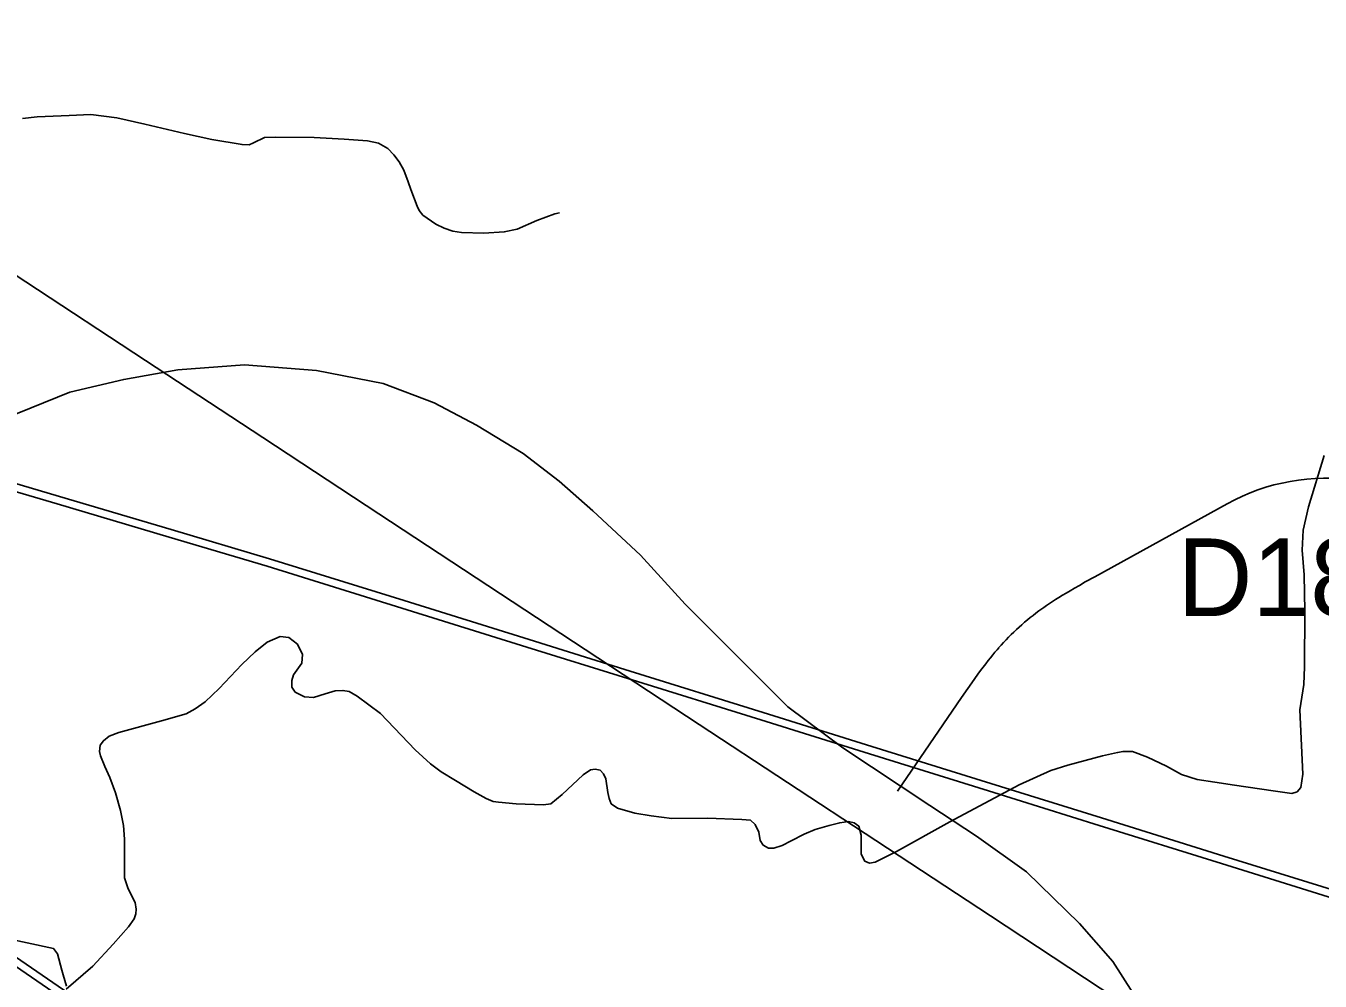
# Model space of a CAD drawing. Extents: x -789162 to -606354, y -1062736 to -945481.
# Drawn here: x -680304 to -677802, y -997921 to -996075 of the extents above; entities that cross this region are included whole.
import ezdxf

# ---------------------------------------------------------------- set-up
doc = ezdxf.new("R2010")
doc.units = 0
for name, color, linetype in [('_SIRSI VZTAHY_ELEKTRICKE VEDENI VN 110 kV S', 7, 'Continuous'), ('_SIRSI VZTAHY_ELEKTRICKE VEDENI VN 400 kV S', 7, 'Continuous'), ('_SIRSI VZTAHY_SILNICE I a II TRIDY_NAVRH POPIS', 7, 'Continuous'), ('_SIRSI VZTAHY_SILNICE I TRIDY_NAVRH', 7, 'Continuous'), ('_SIRSI VZTAHY_SILNICE II TRIDY_REZERVA', 7, 'Continuous'), ('_SIRSI VZTAHY_SILNICE III TRIDY_STAV', 7, 'Continuous'), ('_SIRSI VZTAHY_VTL PLYNOVOD', 7, 'Continuous')]:
    doc.layers.add(name, color=color, linetype=linetype)

msp = doc.modelspace()

# ---------------------------------------------------------------- linework, layer by layer
at = {"layer": '_SIRSI VZTAHY_ELEKTRICKE VEDENI VN 110 kV S'}
for points in [[(-685024.6, -995974.9), (-684755, -996025.3), (-684493.2, -996075.2), (-684240.6, -996121.7), (-684071.4, -996153.5), (-683850.9, -996194), (-683615.6, -996238.7), (-683368.5, -996285.4), (-683140.9, -996327.9), (-682881.3, -996376.3), (-682647.1, -996420.3), (-682428.9, -996460.3), (-682242.2, -996588.2), (-682038.7, -996726.6), (-681844.8, -996858.4), (-681627, -997006.6), (-681415.8, -997150.4), (-681189.1, -997304.7), (-680962, -997459.2), (-680712.5, -997628.8), (-680520.3, -997759.5), (-680366.6, -997864.1), (-680126.8, -998028.5)], [(-685021.9, -995960.1), (-684752.2, -996010.5), (-684490.4, -996060.4), (-684237.8, -996106.9), (-684068.6, -996138.7), (-683848.2, -996179.3), (-683612.8, -996224), (-683365.8, -996270.6), (-683138.2, -996313.1), (-682878.5, -996361.5), (-682644.3, -996405.5), (-682423, -996446.2), (-682233.8, -996575.8), (-682030.3, -996714.2), (-681836.4, -996846), (-681618.5, -996994.2), (-681407.4, -997138), (-681180.7, -997292.3), (-680953.5, -997446.8), (-680704.1, -997616.4), (-680511.8, -997747.1), (-680358.1, -997851.7), (-680114.2, -998019)], [(-677775.7, -997761.4), (-677992.7, -997693.8), (-678228.7, -997620.2), (-678442.9, -997553.6), (-678672.8, -997482), (-678883.3, -997416.4), (-679140.5, -997336.3), (-679335.5, -997275.5), (-679577.6, -997200.1), (-679838.1, -997118.9), (-680027.5, -997062.8), (-680243.8, -996998.8), (-680490, -996926.1)], [(-677775.7, -997761.4), (-677992.7, -997693.8), (-678228.7, -997620.2), (-678442.9, -997553.6), (-678672.8, -997482), (-678883.3, -997416.4), (-679140.5, -997336.3), (-679335.5, -997275.5), (-679577.6, -997200.1), (-679838.1, -997118.9), (-680027.5, -997062.8), (-680243.8, -996998.8), (-680490, -996926.1)], [(-680485.8, -996911.7), (-680239.7, -996984.5), (-680023.2, -997048.4), (-679833.3, -997104.7), (-679573.1, -997185.8), (-679331, -997261.2), (-679136.1, -997322), (-678878.8, -997402.1), (-678668.4, -997467.7), (-678438.5, -997539.2), (-678224.3, -997605.9), (-677988.2, -997679.5), (-677771.4, -997747)], [(-680485.8, -996911.7), (-680239.7, -996984.5), (-680023.2, -997048.4), (-679833.3, -997104.7), (-679573.1, -997185.8), (-679331, -997261.2), (-679136.1, -997322), (-678878.8, -997402.1), (-678668.4, -997467.7), (-678438.5, -997539.2), (-678224.3, -997605.9), (-677988.2, -997679.5), (-677771.4, -997747)]]:
    msp.add_lwpolyline(points, dxfattribs=at)
at = {"layer": '_SIRSI VZTAHY_ELEKTRICKE VEDENI VN 400 kV S'}
msp.add_lwpolyline([(-678166.3, -997975), (-678439.4, -997795), (-678660.8, -997649.5), (-679002.5, -997425.1), (-679222.9, -997280.5), (-679622.1, -997017.8), (-679846.3, -996870.2), (-680073, -996721.2), (-680304.5, -996569.1), (-680758.3, -996270.5), (-680929.3, -996158), (-681000.1, -995927.1), (-681168, -995377.1), (-681221.7, -995201.1), (-681158.1, -994516.5), (-681411, -994089), (-681573.6, -993813.5), (-681729, -993549.7), (-682076.2, -992960.6), (-682198.7, -992719.4), (-682367.5, -992387.1)], dxfattribs=at)
at = {"layer": '_SIRSI VZTAHY_SILNICE I TRIDY_NAVRH'}
msp.add_lwpolyline([(-680430.5, -996867.5), (-680294.1, -996812.9), (-680219.6, -996782.8), (-680115.2, -996758.2), (-680010.7, -996739.8), (-679881.7, -996729.8), (-679742.6, -996740.8), (-679613.3, -996766.1), (-679515.1, -996803.2), (-679433.2, -996846.2), (-679343.1, -996901.5), (-679273.4, -996954.8), (-679207.9, -997012.1), (-679115.7, -997098.1), (-679029.7, -997192.4), (-678913, -997309.1), (-678831.1, -997391), (-678724.6, -997470.6), (-678556.5, -997581.6), (-678466.2, -997641.3), (-678369.5, -997710.1), (-678267.2, -997810.2), (-678202.4, -997883.3), (-678120.8, -998011.5)], dxfattribs=at)
at = {"layer": '_SIRSI VZTAHY_SILNICE II TRIDY_REZERVA'}
for points in [[(-678339.9, -997201.5), (-678336.2, -997198.9), (-678330.8, -997195.1), (-678325.2, -997191.3), (-678319.4, -997187.5), (-678313.3, -997183.5), (-678306.9, -997179.5), (-678300.2, -997175.4), (-678293, -997171), (-678285.3, -997166.5), (-678276.8, -997161.6), (-678267.3, -997156.2), (-678255.8, -997149.7), (-678237.2, -997139.5), (-677981.2, -996998.4)], [(-678619.2, -997554.1), (-678495.1, -997373.2), (-678483, -997355.7), (-678475.5, -997344.9), (-678469.2, -997336), (-678463.5, -997328), (-678458.2, -997320.8), (-678453.2, -997314.1), (-678448.4, -997307.8), (-678443.8, -997301.8), (-678439.3, -997296.1), (-678434.9, -997290.7), (-678430.6, -997285.5), (-678426.3, -997280.6), (-678423.3, -997277.2)]]:
    msp.add_lwpolyline(points, dxfattribs=at)
for centre, radius, start, end in [((-677788.2, -997348.7), 400, 81.7109, 118.8536), ((-678047.9, -997607.4), 500, 125.7291, 138.6656)]:
    msp.add_arc(centre, radius, start, end, dxfattribs=at)
at = {"layer": '_SIRSI VZTAHY_SILNICE III TRIDY_STAV'}
for points in [[(-680311.1, -996253.4), (-680282.5, -996250.3), (-680220.7, -996248.1), (-680178.9, -996245.8), (-680128.7, -996252), (-680074.2, -996264.8), (-679998, -996282.3), (-679945, -996294), (-679886.3, -996303.9), (-679872.6, -996304.5), (-679864, -996300.7), (-679843.1, -996290.2), (-679820.9, -996289.9), (-679746.8, -996290.5), (-679689.1, -996293.7), (-679644, -996296.6), (-679622.4, -996301.3), (-679604.6, -996311.8), (-679592.9, -996323.6), (-679582.4, -996337.1), (-679573.6, -996353.2), (-679565.2, -996376), (-679559.8, -996390.9), (-679547.8, -996422.9), (-679543.7, -996431.5), (-679537, -996440.4), (-679511.8, -996457.9), (-679495.7, -996465.8), (-679478.6, -996471.5), (-679462.1, -996474.1), (-679418.6, -996475.2), (-679379.4, -996472.8), (-679354.2, -996467.4), (-679316.1, -996450.8), (-679281.8, -996437.8), (-679272.6, -996436)], [(-680226.6, -997936.6), (-680175.2, -997892.4), (-680135.7, -997850.1), (-680106.1, -997816.1), (-680095, -997800.9), (-680091.5, -997791.1), (-680091, -997782.3), (-680093.2, -997769.1), (-680106.8, -997742.9), (-680113.5, -997721.4), (-680113.6, -997701.4), (-680113.4, -997668.2), (-680113.5, -997647.2), (-680115.4, -997620.5), (-680121.5, -997591.3), (-680131, -997557.6), (-680142.1, -997527.5), (-680151.6, -997506.5), (-680160.2, -997485.9), (-680162.1, -997477.3), (-680160.5, -997464.9), (-680154.5, -997456.7), (-680143.1, -997447.7), (-680124.6, -997440.5), (-680042.2, -997418.1), (-679994.3, -997404.9), (-679976.8, -997395.1), (-679957.6, -997381.1), (-679930.7, -997355.4), (-679886.6, -997309.5), (-679861, -997284.8), (-679838, -997266.3), (-679812.9, -997255.1), (-679795.8, -997256.8), (-679779.4, -997270), (-679769.8, -997289.8), (-679770.8, -997306.5), (-679786.8, -997329), (-679790.3, -997340), (-679790.3, -997352.8), (-679783.7, -997362.4), (-679765.5, -997371.9), (-679748.4, -997372.7), (-679725.4, -997366), (-679706.5, -997359.9), (-679691.5, -997359.4), (-679679.5, -997361.6), (-679663.7, -997370.4), (-679618.9, -997404.2), (-679551.9, -997474.1), (-679521.9, -997501.1), (-679501.6, -997516.6), (-679473.4, -997533.5), (-679437.6, -997555.7), (-679414.4, -997568.4), (-679401, -997574.4), (-679390.6, -997575.7), (-679356.6, -997578.9), (-679303.6, -997580.8), (-679289.3, -997578.3), (-679267.4, -997560.8), (-679227, -997522.3), (-679212.5, -997512.6), (-679203.6, -997511.3), (-679194.2, -997513.7), (-679187.7, -997520.5), (-679183.2, -997530), (-679179.2, -997557), (-679176.6, -997568.1), (-679172.4, -997578.3), (-679160.4, -997587.2), (-679126.6, -997596.9), (-679095.2, -997602.1), (-679055.1, -997606.7), (-678986.6, -997606.3), (-678919.9, -997608.6), (-678903.5, -997610.3), (-678893.9, -997618.4), (-678887.3, -997633.5), (-678884.5, -997649.7), (-678878.4, -997658.6), (-678868.6, -997664), (-678857.8, -997664), (-678841.9, -997658.9), (-678824.8, -997650), (-678799.4, -997637), (-678778.4, -997628.1), (-678750.8, -997620.2), (-678730.5, -997615.1), (-678713.8, -997612.5), (-678702.5, -997615.1), (-678694, -997622.1), (-678689.4, -997639.5), (-678689.4, -997675.6), (-678682.4, -997689.2), (-678672.8, -997693.1), (-678662, -997691.4), (-678620.8, -997670.5), (-678517.6, -997613.3), (-678383.8, -997541.7), (-678322.5, -997514.1), (-678289.8, -997503.6), (-678222.6, -997485.7), (-678193.3, -997479.5), (-678182.6, -997477.1), (-678164.7, -997477.3), (-678135.2, -997488.4), (-678099.1, -997506), (-678069.6, -997521.7), (-678039.6, -997531.6), (-678005.5, -997536.9), (-677967.1, -997542.6), (-677892.8, -997553.2), (-677856.7, -997558.9), (-677846.2, -997555.4), (-677838.9, -997546.8), (-677835.2, -997521.4), (-677841.2, -997396.7), (-677832.9, -997347.8), (-677831.7, -997314), (-677831.4, -997206), (-677832.5, -997136), (-677836.4, -997088.1), (-677834.8, -997049.3), (-677824, -997004.5), (-677793.9, -996904.9)]]:
    msp.add_lwpolyline(points, dxfattribs=at)
at = {"layer": '_SIRSI VZTAHY_VTL PLYNOVOD'}
msp.add_lwpolyline([(-680226, -997930.9), (-680232, -997909.4), (-680234.6, -997900.1), (-680243.5, -997868.4), (-680250.9, -997858.6), (-680362.4, -997834.6)], dxfattribs=at)

# ---------------------------------------------------------------- texts
at = {"layer": '_SIRSI VZTAHY_SILNICE I a II TRIDY_NAVRH POPIS'}
msp.add_text('D18R', height=150, dxfattribs=at).set_placement((-678077.4, -997215.5))

doc.saveas('drawing.dxf')
